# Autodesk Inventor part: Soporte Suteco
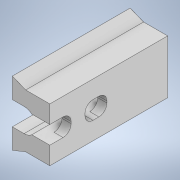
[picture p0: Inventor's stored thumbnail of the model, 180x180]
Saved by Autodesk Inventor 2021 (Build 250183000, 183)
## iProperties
Created: 2021-03
Part Number: Soporte Suteco
Material: Genérico
Document SubType Name: Modeling
Designer: ATOUZA
Density: 1 g/cm^3
Appearance: Valor por defecto
Author: ATOUZA
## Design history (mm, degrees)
sketch "Boceto1"
  geometry: L1 (0.791, -1.4)-(1.963, -1.4) reference; L2 (1.963, -1.4)-(1.963, 1.4) reference; L3 (1.963, 1.4)-(0.791, 1.4) reference; L4 (0.873, -1.6)-(2.163, -1.6); L5 (2.163, -1.6)-(2.163, 1.6); L6 (2.163, 1.6)-(0.873, 1.6); L7 (2.163, 1.6)-(0.723, 1.6); L8 (2.163, -1.6)-(0.723, -1.6); L9 (2.163, -1.6)-(2.163, 1.6); L10 (-2.837, 2.2)-(-2.837, 6); L11 (-2.837, 6)-(-0.337, 5); L12 (-0.337, 5)-(4.163, 5); L13 (4.163, 5)-(4.163, 1.673); L14 (-2.837, 2.2)-(-0.637, 2.2); L15 (0.791, 1.673)-(4.163, 1.673); L16 (-2.637, 0)-(1.963, 0); L17 (-2.837, -2.2)-(-0.637, -2.2); L18 (-2.837, -2.2)-(-2.837, -6); L19 (-2.837, -6)-(-0.337, -5); L20 (-0.337, -5)-(4.163, -5); L21 (4.163, -5)-(4.163, -1.673); L22 (0.791, -1.673)-(4.163, -1.673); A1 r 2 centre (-0.637, 0) between (0.791, 1.4) and (0.791, -1.4) reference; A2 r 2.1 centre (-0.637, 0) between (0.723, 1.6) and (0.723, -1.6); A3 r 2.2 centre (-0.637, 0) between (0.873, 1.6) and (0.873, -1.6); A4 r 2.2 centre (-0.637, 0) between (0.791, 1.673) and (-0.637, 2.2); A5 r 2.2 centre (-0.637, 0) between (0.873, 1.6) and (0.873, -1.6); A6 r 2.2 centre (-0.637, 0) between (0.873, 1.6) and (0.873, -1.6); A7 r 2.2 centre (-0.637, 0) between (0.873, 1.6) and (0.873, -1.6); A8 r 2.2 centre (-0.637, 0) between (0.873, 1.6) and (0.873, -1.6); A9 r 2.2 centre (-0.637, 0) between (-0.637, -2.2) and (0.791, -1.673); 1 further point; 1 other entity
  constraints: 38 end point, 21 point on circle, 16 symmetric about line, 8 centre point, 3 coincident, 2 perpendicular, 2 point on line, 1 horizontal, 1 midpoint, 1 parallel, 1 tangent, 10 other
  dimensions: "d0" = 4.2 diameter of A2; "d1" = 0.2 distance between parallel lines of L3 L6; "d3" = 5 distance between parallel lines of L16 L12; "d4" = 2.5 horizontal distance of L10.end L11.end; "d6" = 7 distance between parallel lines of L13 L10; "d12" = 2.2 distance from line of L18 A1.centre; "d13" = 2 distance between parallel lines of L21 L5 (derived); "d14" = 6 distance from line of L16 L10.end
  node "Referencia1"
node "Plano de trabajo1"
extrude "Extrusión1" new body sketch "Boceto1" stored distance "d7" = 10; taper "d8" = 0 deg
sketch "Boceto2"
  geometry: L1 (1.501, -0.75)-(2.924, -2.173) reference; L2 (2.499, -2.597)-(1.076, -1.174) reference; L3 (7, -2.073)-(7, -1.273) reference; L4 (9.6, -2.473)-(7.4, -2.473) reference; L5 (10, -1.273)-(10, -2.073) reference; L6 (7.4, -0.873)-(9.6, -0.873) reference; L7 (7, -2.073)-(7, -1.273) reference; L8 (7.4, -0.873)-(9.6, -0.873) reference; L9 (10, -1.273)-(10, -2.073) reference; L10 (9.6, -2.473)-(7.4, -2.473) reference; L11 (0, -3.073)-(0, -0.273) reference; L12 (0, -3.073)-(22, -3.073) reference; L13 (22, -0.273)-(22, -3.073) reference; L14 (0, -0.273)-(22, -0.273) reference; L15 (0, 0)-(22, 0) reference; L16 (0, -3.347)-(22, -3.347) reference; L17 (3.972, 0)-(6.553, 0); L18 (6.553, 0)-(6.553, -3.347); L19 (6.553, -3.347)-(3.972, -3.347); L20 (3.972, -3.347)-(3.972, 0); L21 (22, -6.673)-(22, -3.347) reference; L22 (10.652, 0)-(22, 0); L23 (22, 0)-(22, -3.347); L24 (22, -3.347)-(10.652, -3.347); L25 (10.652, -3.347)-(10.652, 0); C1 r 1.25 at (2, -1.673) reference; C2 r 1.25 at (2, -1.673) reference; A1 r 1.05 centre (2, -1.673) between (2.924, -2.173) and (1.501, -0.75) reference; A2 r 1.05 centre (2, -1.673) between (1.076, -1.174) and (2.499, -2.597) reference; A3 r 0.4 centre (7.4, -2.073) between (7, -2.073) and (7.4, -2.473) reference; A4 r 0.4 centre (9.6, -2.073) between (9.6, -2.473) and (10, -2.073) reference; A5 r 0.4 centre (9.6, -1.273) between (10, -1.273) and (9.6, -0.873) reference; A6 r 0.4 centre (7.4, -1.273) between (7.4, -0.873) and (7, -1.273) reference; A7 r 0.4 centre (7.4, -2.073) between (7, -2.073) and (7.4, -2.473) reference; A8 r 0.4 centre (7.4, -1.273) between (7.4, -0.873) and (7, -1.273) reference; A9 r 0.4 centre (9.6, -1.273) between (10, -1.273) and (9.6, -0.873) reference; A10 r 0.4 centre (9.6, -2.073) between (9.6, -2.473) and (10, -2.073) reference; 6 further points
  constraints: 16 end point, 4 parallel, 3 point on line, 2 horizontal, 2 perpendicular
extrude "Extrusión2" join sketch "Boceto2" distance "d9" = 1.7; taper "d10" = 0 deg
fillet "Empalme1" dims "d11" = 1.5
node "Sólido1"
node "Referencia2"
node "Referencia3"
node "Referencia4"
